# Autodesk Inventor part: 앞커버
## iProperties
Company: 한국ATC센터
Created: 2014-11
Part Number: 앞커버
Document SubType Name: Modeling
Designer: KYOUNG IL JANG
Density: 2.71 g/cm^3
Material: 알루미늄-6061
Mass: 204.895 g
Surface Area: 201.401 cm^2
Volume: 75.6071 cm^3
Author: KYOUNG IL JANG
